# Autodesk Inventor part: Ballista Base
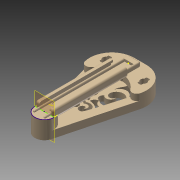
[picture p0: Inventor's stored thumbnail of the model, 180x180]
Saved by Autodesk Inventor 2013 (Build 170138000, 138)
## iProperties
Created: 2013-06
Part Number: Ballista Base
Material: Generic
Document SubType Name: Modeling
Designer: merrill
Density: 1 g/cm^3
Mass: 63.9409 g
Surface Area: 301.661 cm^2
Volume: 63.9409 cm^3
Author: merrill
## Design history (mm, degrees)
sketch "Sketch1"
  geometry: L1 (0, -127)-(0, 127); L2 (0, 0)-(-89.109, 0) reference; L3 (-11.174, 103.82)-(-33.303, 18.956); L4 (-7.416, -14.546)-(0, -14.546); L5 (7.416, -14.546)-(0, -14.546); L6 (11.174, 103.82)-(33.303, 18.956); A1 r 26.752 centre (-7.416, 12.206) between (-33.303, 18.956) and (-7.416, -14.546); A2 r 11.548 centre (0, 100.906) between (0, 112.454) and (-11.174, 103.82); A3 r 26.752 centre (7.416, 12.206) between (7.416, -14.546) and (33.303, 18.956); A4 r 11.548 centre (0, 100.906) between (11.174, 103.82) and (0, 112.454)
  constraints: 12 end point, 8 point on circle, 4 centre point, 4 symmetric about line, 3 point on line, 3 tangent, 2 perpendicular, 1 horizontal, 1 midpoint, 1 vertical, 2 other
  dimensions: "d2" = 127 distance from line of L5 A2.start
extrude "Extrusion1" new body sketch "Sketch1" distance "d4" = 6.35; taper "d5" = 0 deg
sketch "Sketch2"
  geometry: L1 (0, -100.906)-(-23.525, -20.931); L2 (0, -100.906)-(23.525, -20.931); L3 (0, 10.511)-(0, -100.906); L4 (-23.525, -20.931)-(-9.457, -68.756); L5 (9.457, -68.756)-(23.525, -20.931); A1 r 24.521 centre (0, -14.011) between (23.525, -20.931) and (-23.525, -20.931); A2 r 9.858 centre (0, -65.974) between (-9.457, -68.756) and (9.457, -68.756); 1 further point
  constraints: 10 end point, 5 point on circle, 5 tangent, 3 point on line, 2 centre point, 1 collinear, 1 vertical
extrude "Extrusion2" cut sketch "Sketch2" stored distance "d6" = 6.35; taper "d7" = 0 deg
sketch "Sketch3"
  geometry: L1 (7.416, -14.546)-(-7.416, -14.546) reference; L2 (-29.865, 0)-(-22.245, 0); A1 r 3.81 centre (-26.055, 0) between (-29.865, 0) and (-22.245, 0); 1 further point
  constraints: 2 end point, 2 point on circle, 1 centre point, 1 midpoint, 1 parallel, 1 other
  dimensions: "d9" = 3.81 radius of A1
revolve "Revolution1" sketch "Sketch3" stored, may be unused: angle "d8" = 90 deg
mirror "Mirror1"
sketch "Sketch4"
  geometry: L1 (-9.457, -68.756)-(-23.525, -20.931) reference; L2 (0, 10.511)-(0, -75.831); L3 (9.457, -68.756)-(23.525, -20.931); A1 r 8.6 centre (-12.102, -22.626) between (-3.746, -20.593) and (-15.522, -14.735); A2 r 10.754 centre (-11.246, -24.602) between (-15.522, -14.735) and (-21.685, -27.184); A3 r 8.435 centre (-13.254, -27.415) between (-4.821, -27.599) and (-21.685, -27.184); A4 r 4.217 centre (-9.037, -27.507) between (-13.254, -27.415) and (-4.821, -27.599); A5 r 5.516 centre (-8.029, -29.185) between (-13.254, -27.415) and (-3.746, -32.66); A6 r 4.458 centre (-6.137, -36.423) between (-5.466, -40.83) and (-3.746, -32.66); A7 r 3.974 centre (-6.064, -36.901) between (-6.185, -40.873) and (-5.466, -40.83); A8 r 17.027 centre (-0.248, -63.905) between (0, -46.88) and (-13.884, -53.707); A9 r 7.076 centre (-3.736, -56.52) between (0, -50.51) and (-5.448, -63.386); A10 r 2.053 centre (-3.375, -57.59) between (-2.645, -55.672) and (-4.105, -59.509); A11 r 3.758 centre (-3.092, -55.89) between (0, -53.754) and (-4.105, -59.509); A12 r 7.853 centre (-11.998, -35.592) between (-17.59, -41.106) and (-6.185, -40.873); A13 r 6.878 centre (-13.058, -40.613) between (-15.892, -46.88) and (-6.185, -40.873); A14 r 8.707 centre (-16.59, -13.887) between (-9.493, -8.842) and (-24.099, -9.482); A15 r 12.849 centre (0.979, -1.398) between (-4.937, 10.008) and (-9.493, -8.842); A16 r 6.567 centre (-18.474, -7.888) between (-14.991, -2.321) and (-21.377, -1.997); A17 r 7.166 centre (-8.786, 1.265) between (-14.153, 6.014) and (-14.991, -2.321); A18 r 4.126 centre (-4.45, -59.383) between (-5.448, -63.386) and (-2.645, -55.672); A19 r 10.893 centre (-14.609, -19.784) between (-3.746, -20.593) and (-5.415, -13.943); A20 r 19.837 centre (11.329, -3.306) between (-3.092, 10.315) and (-5.415, -13.943); A21 r 6.98 centre (-7.423, -47.743) between (-0.496, -46.88) and (-6.185, -40.873); A22 r 24.521 centre (0, -14.011) between (0, 10.511) and (-23.525, -20.931); A23 r 6.145 centre (-3.711, -70.934) between (-9.457, -68.756) and (0, -75.831); A24 r 17.027 centre (0.248, -63.905) between (13.884, -53.707) and (0, -46.88); A25 r 2.053 centre (3.375, -57.59) between (4.105, -59.509) and (2.645, -55.672); A26 r 3.758 centre (3.092, -55.89) between (4.105, -59.509) and (0, -53.754); A27 r 7.076 centre (3.736, -56.52) between (5.448, -63.386) and (0, -50.51); A28 r 4.126 centre (4.45, -59.383) between (2.645, -55.672) and (5.448, -63.386); A29 r 6.145 centre (3.711, -70.934) between (0, -75.831) and (9.457, -68.756); A30 r 8.6 centre (12.102, -22.626) between (15.522, -14.735) and (3.746, -20.593); A31 r 10.893 centre (14.609, -19.784) between (5.415, -13.943) and (3.746, -20.593); A32 r 8.707 centre (16.59, -13.887) between (24.099, -9.482) and (9.493, -8.842); A33 r 6.567 centre (18.474, -7.888) between (21.377, -1.997) and (14.991, -2.321); A34 r 7.166 centre (8.786, 1.265) between (14.991, -2.321) and (14.153, 6.014); A35 r 24.521 centre (0, -14.011) between (23.525, -20.931) and (0, 10.511); A36 r 19.837 centre (-11.329, -3.306) between (5.415, -13.943) and (3.092, 10.315); A37 r 12.849 centre (-0.979, -1.398) between (9.493, -8.842) and (4.937, 10.008); A38 r 10.754 centre (11.246, -24.602) between (21.685, -27.184) and (15.522, -14.735); A39 r 8.435 centre (13.254, -27.415) between (21.685, -27.184) and (4.821, -27.599); A40 r 4.217 centre (9.037, -27.507) between (4.821, -27.599) and (13.254, -27.415); A41 r 5.516 centre (8.029, -29.185) between (3.746, -32.66) and (13.254, -27.415); A42 r 6.98 centre (7.423, -47.743) between (6.185, -40.873) and (0.496, -46.88); A43 r 6.878 centre (13.058, -40.613) between (6.185, -40.873) and (15.892, -46.88); A44 r 3.974 centre (6.064, -36.901) between (5.466, -40.83) and (6.185, -40.873); A45 r 4.458 centre (6.137, -36.423) between (3.746, -32.66) and (5.466, -40.83); A46 r 7.853 centre (11.998, -35.592) between (6.185, -40.873) and (17.59, -41.106); 1 further point
  constraints: 104 point on circle, 46 centre point, 46 symmetric about line, 11 point on line, 7 tangent, 4 end point, 23 other
extrude "Extrusion3" join sketch "Sketch4" distance "d12" = 6.35; taper "d13" = 0 deg
sketch "Sketch5"
  geometry: L1 (7.416, 14.546)-(-7.416, 14.546) reference; L2 (-33.303, -18.956)-(-11.174, -103.82) reference; L3 (11.174, -103.82)-(33.303, -18.956) reference; L4 (-17.59, -41.106)-(-23.525, -20.931); L5 (23.525, -20.931)-(17.59, -41.106) reference; A1 r 26.752 centre (-7.416, -12.206) between (-7.416, 14.546) and (-33.303, -18.956) reference; A2 r 11.548 centre (0, -100.906) between (-11.174, -103.82) and (11.174, -103.82) reference; A3 r 26.752 centre (7.416, -12.206) between (33.303, -18.956) and (7.416, 14.546) reference; A4 r 24.521 centre (0, -14.011) between (23.525, -20.931) and (-23.525, -20.931) reference; 1 further point
  constraints: 4 end point, 2 point on circle, 2 tangent, 1 centre point, 5 other
extrude "Extrusion4" join sketch "Sketch5" distance "d14" = 2.54; taper "d15" = 0 deg
sketch "Sketch7"
  geometry: L1 (14.831, 0)-(14.831, 8.89) reference; L2 (0, 8.89)-(14.831, 8.89); L3 (14.831, 8.89)-(14.831, 2.947); L4 (14.831, 2.947)-(0, 2.947); L5 (0, 2.947)-(0, 8.89); 1 further point
  constraints: 8 end point, 2 parallel, 1 horizontal, 1 perpendicular, 1 point on line
revolve "Revolution2" sketch "Sketch7" stored, may be unused: angle "d16" = 120 deg
fillet "Fillet1" dims "d17" = 3.175
sketch "Sketch8"
  geometry: C1 r 11.548 at (0, -100.906); A1 r 11.548 centre (0, -100.906) between (-11.174, -103.82) and (11.174, -103.82) reference; 1 further point
  constraints: 1 centre point, 1 coincident
extrude "Extrusion5" join sketch "Sketch8" distance "d18" = 12.7; taper "d19" = 0 deg
sketch "Sketch9"
  geometry: L1 (-11.548, 0)-(11.548, 0); A1 r 11.548 centre (0, 0) between (-11.548, 0) and (11.548, 0); 2 further points; 1 other entity
  constraints: 2 end point, 2 point on circle, 1 centre point, 1 coincident, 1 horizontal, 1 horizontal alignment, 2 other
workplane "Work Plane1"
sketch "Sketch11"
  geometry: L1 (0, 2.971)-(0, -3.81) reference; L2 (-7.62, -1.016)-(0, -1.016); L3 (0, -1.016)-(0, -2.794); L4 (0, -2.794)-(-7.62, -2.794); L5 (-7.62, -2.794)-(-7.62, -1.016); L6 (-7.62, -1.016)-(-5.08, -1.016); L7 (-5.08, -1.016)-(-5.08, 0.566); L8 (-5.08, 0.566)-(-7.62, 0.566); L9 (-7.62, 0.566)-(-7.62, -1.016); L10 (11.548, 0)-(-11.548, 0) reference; L11 (7.62, -2.794)-(7.62, -1.016); L12 (7.62, -1.016)-(5.08, -1.016); L13 (5.08, -1.016)-(5.08, 0.566); L14 (5.08, 0.566)-(7.62, 0.566); L15 (7.62, 0.566)-(7.62, -1.016); L16 (0, -2.794)-(7.62, -2.794); L17 (7.62, -1.016)-(0, -1.016); A1 r 1.27 centre (-6.35, 0.566) between (-5.08, 0.566) and (-7.62, 0.566); A2 r 1.27 centre (6.35, 0.566) between (7.62, 0.566) and (5.08, 0.566); 1 further point
  constraints: 32 end point, 6 symmetric about line, 4 parallel, 4 point on circle, 2 centre point, 2 horizontal, 2 perpendicular, 2 vertical, 1 midpoint, 1 point on line, 1 other
  dimensions: "d20" = 2.54 distance of L7.end L8.end; "d22" = 7.62 distance of L3.end L4.end; "d23" = 1.778 distance between parallel lines of L2 L4; "d24" = 2.032 diameter of L1.end L4; "d25" = 3.81 distance from line of L10 L1.end
extrude "Extrusion6" join sketch "Sketch11" distance "d26" = 5.08; taper "d28" = 0 deg; dims "d27" = 101.6, "d29" = 0
sketch "Sketch12"
  geometry: L1 (-5.08, 0)-(-7.62, 0) reference; L2 (-5.08, 0)-(-5.08, 0.566) reference; L3 (-7.62, 0.566)-(-7.62, 0) reference; A1 r 1.27 centre (-6.35, 0.566) between (-5.08, 0.566) and (-7.62, 0.566) reference; 1 further point
revolve "Revolution3" sketch "Sketch12" stored, may be unused: angle "d30" = 90 deg
sketch "Sketch13"
  geometry: L1 (7.62, 0)-(5.08, 0) reference; L2 (7.62, 0)-(7.62, 0.566) reference; L3 (5.08, 0.566)-(5.08, 0) reference; A1 r 1.27 centre (6.35, 0.566) between (7.62, 0.566) and (5.08, 0.566) reference; 1 further point
revolve "Revolution4" sketch "Sketch13" stored, may be unused: angle "d31" = 90 deg
fillet "Fillet2" dims "d32" = 3.175
fillet "Fillet3" dims "d33" = 5.08
sketch "Sketch14"
  geometry: L1 (0, 7.886)-(0, -5.902) reference; L2 (-6.943, -0.022)-(-6.943, -4.114); L3 (-11.035, 4.31)-(-11.035, -0.022); L4 (-8.491, 6.855)-(-6.096, 6.855); L5 (-6.096, 6.855)-(-6.096, 4.31); L6 (-6.096, 4.31)-(-8.491, 4.31); L7 (-8.491, 4.31)-(-8.491, -0.022); L8 (-8.491, -0.022)-(-6.943, -0.022); L9 (6.943, -0.022)-(6.943, -4.114); L10 (11.035, 4.31)-(11.035, -0.022); L11 (8.491, 6.855)-(6.096, 6.855); L12 (6.096, 6.855)-(6.096, 4.31); L13 (6.096, 4.31)-(8.491, 4.31); L14 (8.491, 4.31)-(8.491, -0.022); L15 (8.491, -0.022)-(6.943, -0.022); A1 r 4.092 centre (-6.943, -0.022) between (-11.035, -0.022) and (-6.943, -4.114); A2 r 2.545 centre (-8.491, 4.31) between (-8.491, 6.855) and (-11.035, 4.31); A3 r 4.092 centre (6.943, -0.022) between (6.943, -4.114) and (11.035, -0.022); A4 r 2.545 centre (8.491, 4.31) between (11.035, 4.31) and (8.491, 6.855); 1 further point
  constraints: 30 end point, 9 symmetric about line, 8 point on circle, 4 centre point, 4 parallel, 2 perpendicular, 2 vertical, 1 tangent, 2 other
extrude "Extrusion7" join sketch "Sketch14" distance "d34" = 88.9; taper "d35" = 0 deg
fillet "Fillet4" dims "d36" = 2.54
fillet "Fillet5" dims "d37" = 2.54
sketch "Sketch16"
  geometry: C1 r 5.08 at (7.62, 6.35); 1 further point
  constraints: 1 centre point
  dimensions: "d38" = 10.16 diameter of C1
extrude "Extrusion8" join sketch "Sketch16" distance "d40" = 7.112; taper "d41" = 0 deg
sketch "Sketch17"
  geometry: L1 (-5.08, 0)-(5.08, 0); A1 r 5.08 centre (0, 0) between (-5.08, 0) and (5.08, 0) reference; A2 r 5.08 centre (0, 0) between (5.08, 0) and (-5.08, 0); 1 further point
  constraints: 4 point on circle, 2 end point, 1 centre point, 1 coincident, 1 horizontal
revolve "Revolution5" sketch "Sketch17" stored, may be unused: angle "d42" = 45 deg
sketch "Sketch18"
  geometry: L1 (5.08, 0.566)-(5.08, -1.016) reference; L2 (5.08, -1.016)-(-5.08, -1.016) reference; L3 (-5.08, -1.016)-(-5.08, 0.566) reference; L4 (-7.62, 0.566)-(-7.62, -2.794) reference; L5 (-7.62, -2.794)-(7.62, -2.794) reference; L6 (7.62, -2.794)-(7.62, 0.566) reference; L7 (-7.62, -2.794)-(7.62, -2.794); L8 (-7.62, -2.794)-(-7.62, 0.566); L9 (-6.35, 1.836)-(6.35, 1.836); A1 r 1.27 centre (6.35, 0.566) between (7.62, 0.566) and (5.08, 0.566) reference; A2 r 1.27 centre (-6.35, 0.566) between (-5.08, 0.566) and (-7.62, 0.566) reference; A3 r 1.27 centre (-6.35, 0.566) between (-6.35, 1.836) and (-7.62, 0.566); A4 r 1.27 centre (6.35, 0.566) between (7.62, 0.566) and (6.35, 1.836); 1 further point
  constraints: 6 end point, 6 point on circle, 2 centre point, 2 coincident, 2 collinear, 1 tangent
extrude "Extrusion9" join sketch "Sketch18" distance "d43" = 7.62; taper "d44" = 0 deg
fillet "Fillet6" dims "d45" = 2.54
sketch "Sketch19"
  geometry: L1 (7.416, 14.546)-(-7.416, 14.546) reference; L2 (-7.416, 14.546)-(7.416, 14.546); A1 r 26.752 centre (7.416, -12.206) between (33.303, -18.956) and (7.416, 14.546) reference; A2 r 26.752 centre (-7.416, -12.206) between (-7.416, 14.546) and (-33.303, -18.956) reference; A3 r 5.551 centre (-27.931, -17.556) between (-33.303, -18.956) and (-23.525, -20.931); A4 r 5.551 centre (27.931, -17.556) between (23.525, -20.931) and (33.303, -18.956); A5 r 26.752 centre (-7.416, -12.206) between (-7.416, 14.546) and (-33.303, -18.956); A6 r 26.752 centre (7.416, -12.206) between (33.303, -18.956) and (7.416, 14.546); A7 r 29.631 centre (0, -38.947) between (23.525, -20.931) and (-23.525, -20.931); 1 further point
  constraints: 11 point on circle, 10 tangent, 5 centre point, 2 end point, 1 collinear, 1 concentric
extrude "Extrusion10" join sketch "Sketch19" distance "d46" = 7.62; taper "d47" = 0 deg
sketch "Sketch21"
  geometry: L1 (0, 18.804)-(0, -25.062) reference; C1 r 3.81 at (-22.826, -4.055); C2 r 3.81 at (22.826, -4.055); 1 further point
  constraints: 2 centre point, 2 end point, 1 symmetric about line, 1 vertical, 1 other
  dimensions: "d48" = 7.62 diameter of C1
extrude "Extrusion11" cut sketch "Sketch21" distance "d50" = 7.62; taper "d51" = 0 deg
sketch "Sketch22"
  geometry: L1 (7.416, 14.546)-(-7.416, 14.546) reference; L2 (0, 25.142)-(0, -17.556); L3 (-22.826, 5.017)-(-22.826, -11.576); L4 (-25.112, 1.279)-(-20.54, 1.279); L5 (-20.54, 1.279)-(-20.54, -9.389); L6 (-20.54, -9.389)-(-25.112, -9.389); L7 (-25.112, -9.389)-(-25.112, 1.279); L8 (-25.112, 1.279)-(-20.54, -9.389); L9 (20.54, 1.279)-(20.54, -9.389); L10 (22.826, 5.017)-(22.826, -11.576); L11 (25.112, 1.279)-(20.54, 1.279); L12 (25.112, -9.389)-(25.112, 1.279); L13 (25.112, 1.279)-(20.54, -9.389); L14 (20.54, -9.389)-(25.112, -9.389); C1 r 3.81 at (-22.826, -4.055) reference; A1 r 5.803 centre (-22.826, -4.055) between (-20.54, 1.279) and (-25.112, 1.279); A2 r 5.803 centre (-22.826, -4.055) between (-25.112, -9.389) and (-20.54, -9.389); A3 r 5.803 centre (22.826, -4.055) between (25.112, 1.279) and (20.54, 1.279); A4 r 5.803 centre (22.826, -4.055) between (20.54, -9.389) and (25.112, -9.389); 4 further points
  constraints: 26 end point, 10 symmetric about line, 8 point on circle, 6 coincident, 4 centre point, 3 parallel, 2 perpendicular, 1 horizontal, 1 midpoint, 2 other
  dimensions: "d52" = 4.572 distance of L4.start L4.end; "d54" = 10.668 distance of L6.end L4.start
extrude "Extrusion12" cut sketch "Sketch22" distance "d55" = 7.62; taper "d56" = 0 deg
sketch "Sketch23"
  geometry: L1 (-25.112, -1.007)-(-25.112, 1.279) reference; L2 (0, 23.289)-(0, -17.552); C1 r 5.842 at (-22.826, -4.055); C2 r 5.842 at (22.826, -4.055); A1 r 5.803 centre (-22.826, -4.055) between (-20.54, 1.279) and (-25.112, 1.279) reference; 1 further point
  constraints: 2 centre point, 2 end point, 1 coincident, 1 parallel, 1 symmetric about line, 1 other
  dimensions: "d57" = 11.684 diameter of C1
extrude "Extrusion13" cut sketch "Sketch23" distance "d59" = 4.064; taper "d60" = 0 deg
body "Solid1"
